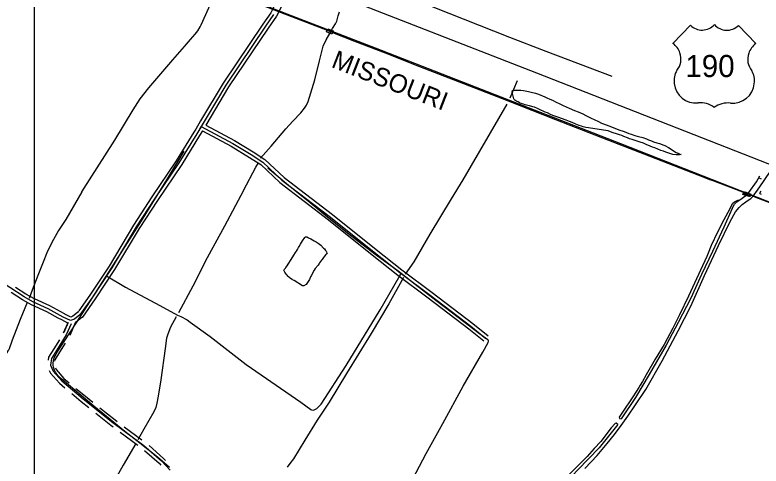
# Model space of a CAD drawing. Extents: x 3281947 to 3319794, y 715894 to 741249.
# Drawn here: x 3291243 to 3294621, y 723513 to 725556 of the extents above; entities that cross this region are included whole.
import ezdxf

# ---------------------------------------------------------------- set-up
doc = ezdxf.new("R2010")
doc.units = 0
for name, color, linetype in [('V-BRDG-OTLN', 7, 'Continuous'), ('V-DTCH-CNTR', 7, 'Continuous'), ('V-GRID-MAJR', 7, 'Continuous'), ('V-RAIL-IDEN', 7, 'Continuous'), ('V-RAIL-TRAK', 7, 'Continuous'), ('V-ROAD-CNTR', 7, 'Continuous'), ('V-ROAD-IDEN', 7, 'Continuous'), ('V-SITE-VEGE', 7, 'Continuous'), ('V-TOPO-SHOR', 7, 'Continuous')]:
    doc.layers.add(name, color=color, linetype=linetype)

msp = doc.modelspace()

# ---------------------------------------------------------------- linework, layer by layer
at = {"layer": 'V-BRDG-OTLN'}
for points in [[(3292653.9, 725479.3), (3292659.4, 725492.5), (3292683.8, 725483.4), (3292678, 725469.1)], [(3294547.7, 724753.5), (3294546.2, 724749.7), (3294544.5, 724745.1), (3294567.7, 724735.7), (3294566.6, 724733.2), (3294538.4, 724743.2), (3294543.2, 724755.1)], [(3294567.7, 724735.7), (3294544.5, 724745.1), (3294546.2, 724749.7), (3294547.7, 724753.5), (3294571.6, 724744.6)], [(3294567.7, 724735.7), (3294571.6, 724744.6), (3294547.7, 724753.5), (3294548, 724754.2), (3294574.4, 724744.5), (3294572.6, 724739.5), (3294570.9, 724734.4)]]:
    msp.add_lwpolyline(points, close=True, dxfattribs=at)
at = {"layer": 'V-DTCH-CNTR'}
for points in [[(3291942.7, 723506.4), (3291889.3, 723554.4), (3291808.9, 723616.7), (3291741, 723670.1), (3291658.5, 723737.3), (3291601, 723783.9), (3291456.8, 723905.8), (3291437.4, 723923), (3291427.6, 723938.1), (3291422.7, 723947), (3291417.8, 723960.8), (3291417.1, 723969.8), (3291417, 723979.4), (3291418.4, 723990.5), (3291421.7, 724002.9), (3291425.1, 724011.2), (3291430.6, 724021.6), (3291437.4, 724033.4), (3291524.3, 724164.9), (3291651.5, 724365.7), (3291657.3, 724374.9), (3291816.3, 724623.3), (3291938.7, 724820.7), (3292009.7, 724939.1)], [(3293013.8, 723398.5), (3293105.3, 723570.9), (3293180.4, 723706.5), (3293272.4, 723875.3), (3293360.5, 724029.3), (3293385.1, 724073.3), (3293387.3, 724079.3), (3293386.7, 724081.1), (3293383.1, 724084.6), (3293346.2, 724111.6), (3293224.2, 724205.2), (3293149.2, 724262.2), (3293054.6, 724335.8), (3292990.9, 724385.3), (3292984.3, 724390.5), (3292878.4, 724468.7), (3292762.3, 724557.5), (3292657.5, 724639.9), (3292579.5, 724705.3), (3292481.3, 724783.5), (3292388.4, 724861.8)], [(3294584.6, 724734.7), (3294604.3, 724761.8), (3294630.9, 724801.3), (3294647.3, 724824.2), (3294669.8, 724855.4), (3294688, 724881.7)], [(3294504.6, 724663.7), (3294521, 724683.8), (3294535.3, 724697), (3294551.1, 724708.9), (3294566.9, 724720), (3294573.7, 724724.9), (3294579.2, 724729.1), (3294584.6, 724734.7)], [(3293822.8, 723502.5), (3293879.2, 723561), (3293924, 723615.3), (3293957, 723657), (3293987.9, 723697.4), (3294017.4, 723739.1), (3294052.5, 723789.9), (3294098.5, 723860.1), (3294173.2, 723989.3), (3294245.9, 724125.5), (3294302, 724237.3), (3294364.9, 724376.2), (3294427.9, 724512.3), (3294480.6, 724619.9), (3294504.6, 724663.7)], [(3291657.3, 724374.9), (3291744.6, 724323.7), (3291898.9, 724239.7), (3291979.8, 724196.7), (3291994.3, 724189.9), (3292022.7, 724175.6), (3292037.3, 724165.3), (3292127.3, 724099.6), (3292290.1, 723973.6), (3292537.4, 723802.5), (3292582.4, 723769), (3292585.9, 723768.3), (3292595.5, 723767), (3292610, 723774.7), (3292618.2, 723782.3), (3292629.2, 723794.1), (3292742.7, 723969.3), (3292895.8, 724220.6), (3292980.5, 724366.6), (3292990.9, 724385.3)]]:
    msp.add_lwpolyline(points, dxfattribs=at)
at = {"layer": 'V-GRID-MAJR'}
msp.add_spline([(3291333.3, 721274), (3291331.5, 727333.8), (3291329.7, 733395.6), (3291328, 739457.3), (3291328, 739459.2)], degree=3, dxfattribs=at)
at = {"layer": 'V-RAIL-TRAK'}
for p, q in [((3294572.6, 724739.5), (3294546.2, 724749.7)), ((3294584.6, 724734.7), (3294572.6, 724739.5))]:
    msp.add_line(p, q, dxfattribs=at)
for points in [[(3292170, 725674.9), (3292307.9, 725621.4), (3292443.6, 725568.5), (3292656.7, 725486.1), (3292680.9, 725476.4), (3292780, 725437.2), (3292919.1, 725383.8), (3293074.5, 725323), (3293273.2, 725245.4), (3293476.3, 725166.5), (3293689.9, 725082.3), (3293930, 724989), (3294117, 724916.3), (3294333.8, 724831.5), (3294391.4, 724809.7)], [(3294546.2, 724749.7), (3294486.1, 724773.3), (3294391.4, 724809.7)], [(3295596.8, 724339.4), (3295590.1, 724342), (3295495.8, 724379), (3295404.7, 724414.1), (3295300, 724455), (3295207.5, 724491), (3295113.3, 724528.4), (3295017.6, 724565.8), (3294919.7, 724603.6), (3294791.3, 724654.3), (3294691.5, 724693.4), (3294596.8, 724729.9), (3294584.6, 724734.7)]]:
    msp.add_lwpolyline(points, dxfattribs=at)
at = {"layer": 'V-ROAD-CNTR'}
for points in [[(3287528.8, 727489.4), (3288159.7, 727246.7), (3289159.6, 726857.6), (3289743.7, 726626.7), (3290210.1, 726446.4), (3290854.7, 726194.3), (3291198.3, 726062.1), (3292329.9, 725616.5), (3292874.1, 725407.4), (3293983.9, 724974.1), (3294772.1, 724664.7), (3295711.6, 724298), (3296794.9, 723876.7), (3297613.5, 723554.1), (3297991.8, 723406.1), (3298815.4, 723086.6), (3299719.3, 722731.4), (3300678.1, 722358.1)], [(3287937.3, 727504.7), (3287942.9, 727501.7), (3288375.3, 727335.2), (3289142.9, 727037.7), (3290162.7, 726638), (3290851.4, 726368), (3291373.2, 726163.1), (3292434, 725750.1), (3293604.8, 725293.3), (3294762.1, 724839.9)], [(3292483.1, 725732.1), (3292453.4, 725669.1), (3292422.6, 725607.3), (3292401.3, 725564.8), (3292365.5, 725513.2), (3292185.2, 725246.4), (3292084, 725076.1)], [(3292510.3, 725719.2), (3292480.4, 725656.1), (3292449.5, 725593.9), (3292427.1, 725549.4), (3292390.3, 725496.3), (3292210.5, 725230.3), (3292107.2, 725056.3)], [(3292414.2, 725557.1), (3292377.9, 725504.7), (3292197.8, 725238.4), (3292066.6, 725017.4), (3291985.7, 724886.6), (3291875.8, 724723.7), (3291792.7, 724596.1), (3291681.9, 724410.9), (3291594.9, 724278.6), (3291537.8, 724198.2), (3291513.6, 724178.7), (3291495.1, 724171.8), (3291462.2, 724188.2), (3291393.9, 724224.7), (3291324.6, 724257.2), (3291285.4, 724279.3), (3291153.5, 724363.4)], [(3292084, 725076.1), (3292061.9, 725038.9)], [(3292107.2, 725056.3), (3292236.5, 724987), (3292321.2, 724936.3), (3292374.4, 724901.7), (3292461.7, 724819.7), (3292680.5, 724652.3), (3292878.5, 724493.4), (3292994.2, 724401.9), (3293132.1, 724299.4), (3293316.3, 724158.1), (3293385.1, 724102.8)], [(3292061.9, 725038.9), (3292053.8, 725025.2), (3291973.1, 724894.8), (3291863.3, 724732), (3291780, 724604.1), (3291669.2, 724418.9), (3291582.6, 724287.1), (3291532.3, 724216.2)], [(3292091.8, 725030.5), (3292079.4, 725009.6), (3291998.3, 724878.5), (3291888.3, 724715.4), (3291805.4, 724588.2), (3291694.6, 724402.9), (3291607.3, 724270.1), (3291548.8, 724187.8), (3291538.6, 724179.6)], [(3292080.5, 725040.7), (3292086.3, 725050.5), (3292229.1, 724974), (3292313.3, 724923.5), (3292365.1, 724889.8), (3292452, 724808.2), (3292671.3, 724640.5), (3292869.1, 724481.7), (3292985, 724390), (3293123, 724287.4), (3293307.1, 724146.3), (3293375.2, 724091.6)], [(3292091.8, 725030.5), (3292221.7, 724960.9), (3292305.3, 724910.8), (3292355.8, 724878), (3292442.3, 724796.8), (3292662, 724628.7), (3292859.8, 724470), (3292975.9, 724378.1), (3293114, 724275.4), (3293297.8, 724134.5), (3293365.2, 724080.3)], [(3291467.7, 724202.2), (3291400.7, 724238.2), (3291331.5, 724270.6), (3291293.1, 724292.2), (3291246.4, 724322)], [(3291439.4, 724183.4), (3291387.2, 724211.3), (3291317.8, 724243.9), (3291277.7, 724266.5), (3291226.7, 724298.9)], [(3291530.9, 724214.3), (3291526.8, 724208.6), (3291506, 724191.9), (3291496, 724188.1), (3291469.1, 724201.5), (3291467.7, 724202.2)], [(3291483.6, 724160.8), (3291455.3, 724174.9), (3291439.4, 724183.4)], [(3291538.6, 724179.6), (3291521.1, 724165.5), (3291518.1, 724164.4)], [(3291498.3, 724156.9), (3291476, 724107), (3291432, 724036.3), (3291409.6, 724000.3), (3291404.8, 723970.7), (3291416.9, 723942.8), (3291455, 723899.4), (3291553, 723817.6), (3291687.2, 723710.7), (3291827.5, 723606.1), (3291906.1, 723536.6), (3291945.7, 723495.5)], [(3291463.6, 724116.1), (3291483.6, 724160.8)], [(3291484.6, 724163.1), (3291464.2, 724117.4)], [(3291518.1, 724164.4), (3291491.6, 724105.2)], [(3291512, 724150.8), (3291491.6, 724105.2)], [(3291444.6, 724084.9), (3291419.3, 724044.2), (3291395.3, 724005.7), (3291393.2, 723993.2)], [(3291444.6, 724084.9), (3291419.3, 724044.2), (3291395.3, 724005.7), (3291393.2, 723993.2)], [(3291470.1, 724069.1), (3291444.8, 724028.3), (3291423.9, 723995), (3291422.9, 723988.4)], [(3291470.1, 724069.1), (3291444.8, 724028.3), (3291423.9, 723995), (3291422.9, 723988.4)], [(3291398.8, 723946.7), (3291404, 723934.6), (3291444.5, 723888.6), (3291469.6, 723867.7)], [(3291398.8, 723946.7), (3291404, 723934.6), (3291444.5, 723888.6), (3291469.6, 723867.7)], [(3291426.4, 723958.6), (3291429.7, 723950.9), (3291465.5, 723910.2), (3291488.8, 723890.7)], [(3291426.4, 723958.6), (3291429.7, 723950.9), (3291465.5, 723910.2), (3291488.8, 723890.7)], [(3291500.3, 723842.1), (3291543.5, 723806), (3291577.9, 723778.6)], [(3291500.3, 723842.1), (3291543.5, 723806), (3291577.9, 723778.6)], [(3291519.5, 723865.1), (3291562.5, 723829.2), (3291596.6, 723802)], [(3291519.5, 723865.1), (3291562.5, 723829.2), (3291596.6, 723802)], [(3291627.9, 723777.1), (3291696.4, 723722.6), (3291706, 723715.4)], [(3291627.9, 723777.1), (3291696.4, 723722.6), (3291706, 723715.4)], [(3291609.2, 723753.6), (3291678.1, 723698.8), (3291688.1, 723691.4)], [(3291609.2, 723753.6), (3291678.1, 723698.8), (3291688.1, 723691.4)], [(3291738.1, 723691.5), (3291818.2, 723631.7)], [(3291738.1, 723691.5), (3291818.2, 723631.7)], [(3291720.1, 723667.4), (3291800.3, 723607.7)], [(3291720.1, 723667.4), (3291800.3, 723607.7)], [(3291850.4, 723605.9), (3291916.5, 723547.5), (3291925.5, 723538.1)], [(3291850.4, 723605.9), (3291916.5, 723547.5), (3291925.5, 723538.1)], [(3291830.5, 723583.4), (3291895.7, 723525.8), (3291903.9, 723517.3)], [(3291830.5, 723583.4), (3291895.7, 723525.8), (3291903.9, 723517.3)]]:
    msp.add_lwpolyline(points, dxfattribs=at)
at = {"layer": 'V-ROAD-IDEN'}
for p, q in [((3294221.8, 725427), (3294300.9, 725508.7)), ((3294596.8, 725425.8), (3294518, 725507.9))]:
    msp.add_line(p, q, dxfattribs=at)
for centre, major_axis, start_param, end_param in [((3294353.6, 725562), (0, -75), 5.502702, 7.121811), ((3294465.5, 725561.4), (0, 75), 2.291842, 3.917604), ((3294166.5, 725353.3), (0, 92.2), 5.045266, 5.638568), ((3294651.7, 725351.8), (0, -92.2), 3.781672, 4.374974), ((3294176.6, 725356.4), (0, 81.7), 4.021008, 5.049788), ((3294641.7, 725355), (0, -81.7), 4.370452, 5.399232), ((3294312.9, 725259.2), (0, -86.5), 4.163028, 4.868958), ((3294504.8, 725258.4), (0, 86.5), 4.551282, 5.257212), ((3294325.8, 725255.7), (0, 98.8), 1.672766, 3.238327), ((3294492, 725255), (0, -98.8), 6.181885, 7.747479), ((3294346.1, 725052.3), (0, 105.6), 5.646836, 6.385311), ((3294470.8, 725051.6), (0, -105.6), 3.034929, 3.773404)]:
    msp.add_ellipse(centre, major_axis=major_axis, ratio=0.99789, start_param=start_param, end_param=end_param, dxfattribs=at)
at = {"layer": 'V-SITE-VEGE'}
for points in [[(3294236, 724933.6), (3294245.2, 724930.6), (3294253.1, 724925.9), (3294258.5, 724924.1), (3294251, 724923), (3294236.7, 724923.1), (3294220.8, 724924.6), (3294212.8, 724926.4), (3294202.8, 724930.3), (3294189.9, 724934.2), (3294178.2, 724938.6), (3294166.9, 724942.5), (3294154, 724948.1), (3294139.8, 724953.3), (3294129.8, 724957.2), (3294118.9, 724962), (3294101, 724969.3), (3294088.9, 724974.5), (3294073, 724980.2), (3294050, 724987.2), (3294037.5, 724991.6), (3294025.8, 724995.1), (3294016.2, 724999.4), (3293998.7, 725005.5), (3293990.3, 725009.4), (3293980.3, 725012.4), (3293970.3, 725016.3), (3293946.1, 725024.2), (3293936, 725027.7), (3293931.4, 725029), (3293929, 725030.7), (3293926.4, 725031.6), (3293838.9, 725045.3), (3293828.1, 725045.9), (3293815.9, 725049), (3293807.2, 725052), (3293797.5, 725055.1), (3293782.5, 725061.6), (3293766.3, 725068.1), (3293752.9, 725073.7), (3293738.3, 725079.3), (3293700.3, 725093.2), (3293678.6, 725100.6), (3293667.7, 725105), (3293653.6, 725111.9), (3293643.1, 725115.8), (3293618.1, 725128.3), (3293609, 725132.6), (3293595.2, 725137.8), (3293587.2, 725139.6), (3293573, 725143.5), (3293564.7, 725146.2), (3293552.1, 725149.3), (3293545, 725151.5), (3293535, 725154.9), (3293527.9, 725158), (3293520.4, 725162.3), (3293516.7, 725164), (3293510.4, 725167.4), (3293505.4, 725170.4), (3293502.5, 725173.4), (3293501.3, 725175.9), (3293499.7, 725181.4), (3293498.1, 725187.7), (3293495.3, 725199.9), (3293493.7, 725207.5), (3293495.9, 725214.2), (3293501.4, 725215.8), (3293516.9, 725215.6), (3293528.2, 725214.6), (3293532.8, 725214.5), (3293545.4, 725213.5), (3293568.4, 725209.5), (3293580.1, 725206.8), (3293598.9, 725201.5), (3293613.1, 725196.3), (3293641.1, 725185.4), (3293654, 725179.4), (3293661.5, 725175.5), (3293679.9, 725167.7), (3293690.7, 725161.7), (3293709.9, 725152.7), (3293725.3, 725146.2), (3293738.2, 725139.7), (3293752, 725134.1), (3293775.4, 725123.7), (3293792.1, 725117.2), (3293813.7, 725107.3), (3293827.9, 725100), (3293850.8, 725088.8), (3293864.6, 725082.3), (3293884.6, 725073.2), (3293898.8, 725066.3), (3293918.8, 725058.5), (3293932.2, 725052.9), (3293958.9, 725042.5), (3293977.3, 725035.5), (3294000.2, 725027.7), (3294011.5, 725023.4), (3294021.9, 725019), (3294033.2, 725015.5)], [(3294033.2, 725015.5), (3294049.1, 725010.3), (3294059.9, 725007.2), (3294066.2, 725005.9), (3294085.9, 725000.6), (3294101.7, 724994.9), (3294111.7, 724991), (3294124.3, 724985), (3294133.4, 724981.9), (3294148.5, 724977.1), (3294161.4, 724973.2), (3294180.2, 724966.6), (3294185.6, 724964.1), (3294201.1, 724956.3), (3294209, 724950.8), (3294219.8, 724943.5), (3294236, 724933.6)], [(3294622.8, 724742.4), (3294616.6, 724746.2), (3294614.5, 724749.2), (3294615.8, 724752.5), (3294621.3, 724757.5)]]:
    msp.add_lwpolyline(points, dxfattribs=at)
msp.add_lwpolyline([(3292507.8, 724353.6), (3292500.3, 724356.6), (3292497.8, 724357.9), (3292490.8, 724362.6), (3292487.9, 724365.2), (3292482, 724369.9), (3292479.1, 724372.4), (3292475.4, 724377.1), (3292473, 724380.9), (3292468, 724387.2), (3292465.1, 724391.5), (3292461.4, 724397.4), (3292461, 724399.9), (3292461.5, 724402.8), (3292463.2, 724404.5), (3292467.5, 724409.1), (3292469.6, 724411.6), (3292476, 724420.3), (3292480.7, 724427.3), (3292493.1, 724448.6), (3292505.6, 724468.6), (3292513.7, 724479.8), (3292517.9, 724486.4), (3292522.2, 724493.5), (3292527, 724502.7), (3292530, 724507.7), (3292535.5, 724517.7), (3292545, 724533.5), (3292555.2, 724547.6), (3292558.2, 724550.5), (3292560.3, 724550.9), (3292564.5, 724550.8), (3292567.8, 724549.1), (3292572.4, 724546.6), (3292582, 724541.8), (3292597.4, 724532.8), (3292606.2, 724528.9), (3292616.6, 724522.5), (3292621.5, 724518.2), (3292627.8, 724512.7), (3292639.8, 724500.4), (3292644.3, 724496.1), (3292648.9, 724489.4), (3292651.8, 724486), (3292655.5, 724480.9), (3292655.9, 724478.8), (3292654.1, 724474.6), (3292650.7, 724470.5), (3292644.3, 724463.4), (3292640.1, 724458), (3292633.6, 724448.4), (3292631.1, 724445.5), (3292622.1, 724433.9), (3292620.8, 724431), (3292615.3, 724423.5), (3292602.1, 724407.3), (3292597.4, 724400.7), (3292583.6, 724375.3), (3292581, 724369.8), (3292576.3, 724358.6), (3292571.1, 724349), (3292567.7, 724344), (3292564.7, 724340.3), (3292560.9, 724335.7), (3292550.7, 724330), (3292547.8, 724329.2), (3292545.3, 724328.8)], close=True, dxfattribs=at)
at = {"layer": 'V-TOPO-SHOR'}
for p, q in [((3293485.6, 725179.9), (3293518.7, 725258.3)), ((3294622.7, 724811.6), (3294609.6, 724817.8))]:
    msp.add_line(p, q, dxfattribs=at)
for points in [[(3291546.3, 724755.1), (3291696.2, 724989.2), (3291778, 725126.5), (3291809.5, 725176.5), (3291848.9, 725226.2), (3291957.5, 725351.9), (3292010.9, 725413.4), (3292038.1, 725444.5), (3292059, 725468.8), (3292071.2, 725483.9), (3292081.7, 725501.6), (3292087.1, 725510.2), (3292134.6, 725618), (3292159.1, 725681.9), (3292193.8, 725775.5)], [(3293946.3, 725277.6), (3293648.5, 725389.8), (3293484, 725454.2), (3293136.2, 725591.4), (3292912.6, 725682.6)], [(3292355.1, 724906.9), (3292402.5, 724961.6), (3292470.3, 725039.6), (3292501.5, 725074.5), (3292537.7, 725112.2), (3292554.4, 725134.3), (3292563.6, 725146.7), (3292571.1, 725163.7), (3292600.5, 725261.5), (3292621.3, 725347.3), (3292639.1, 725414.1), (3292652.1, 725443.2), (3292669.1, 725471.2), (3292681.3, 725494.4), (3292695.1, 725515.4), (3292699.8, 725527.9), (3292704.1, 725539.2), (3292706.7, 725550.9), (3292712.3, 725569.7)], [(3293469.6, 725151.9), (3293270.2, 724809.6), (3293217.9, 724723.1)], [(3292277.2, 724760.5), (3292333.3, 724866.2), (3292345.8, 724886.5)], [(3294525.1, 724718.1), (3294552.2, 724738.1), (3294559.1, 724744.5), (3294565.2, 724752.1), (3294599.4, 724800.4), (3294615.2, 724827.5)], [(3291546.3, 724755.1), (3291473.5, 724630.3), (3291440.6, 724579.1), (3291410.1, 724526.2), (3291387.8, 724479.2), (3291371.5, 724435.9), (3291346.9, 724375.9), (3291321.8, 724309.9), (3291307.9, 724272.1)], [(3292277.2, 724760.5), (3292192.1, 724600), (3292114.1, 724456.7), (3292047.9, 724327.1), (3291983.7, 724206.8)], [(3293217.9, 724723.1), (3293121.6, 724562.5), (3293048.9, 724437.6), (3293010.4, 724382.2)], [(3294479.3, 724678.2), (3294492.2, 724703.1), (3294500.5, 724710.1), (3294509.4, 724714.3), (3294514.9, 724716.4), (3294525.1, 724718.1)], [(3294489.7, 724679.6), (3294500.6, 724699), (3294511.5, 724709.4), (3294525.1, 724718.1)], [(3294479.3, 724678.2), (3294451.3, 724628.2), (3294423.3, 724572.8), (3294395.3, 724512.5), (3294381.7, 724476.5), (3294375.5, 724462.7), (3294346.2, 724399.6), (3294310, 724322), (3294292.2, 724282.6), (3294251.9, 724197.4), (3294221.8, 724138.4), (3294181.5, 724063.6), (3294141.8, 723997.7), (3294100.7, 723927), (3294084.3, 723895.8), (3294072.7, 723879.2), (3294067.9, 723868.8), (3294039.8, 723826.5), (3293993.2, 723757.8), (3293978.1, 723734.2), (3293980, 723729.1), (3293986.8, 723726.6)], [(3294489.7, 724679.6), (3294452.2, 724595.1), (3294400, 724484.3), (3294351.3, 724381.3), (3294302.6, 724273), (3294245.6, 724162.8), (3294191.6, 724060.9), (3294114.5, 723928.1), (3294051.6, 723823.2), (3293986.8, 723726.6)], [(3293001.5, 724367.6), (3292935.6, 724247.9), (3292855.1, 724113.5), (3292744.7, 723932.1), (3292665.5, 723801.9), (3292612, 723721), (3292556.2, 723630), (3292504, 723546.1), (3292488.1, 723524.7), (3292475.7, 723508)], [(3291299, 724253.4), (3291266.9, 724176.9), (3291230.6, 724083.6), (3291215.5, 724040.3), (3291212, 724034.9), (3291161.4, 723956.4), (3291116.2, 723883.2), (3291108, 723867.8), (3291102.8, 723852.3), (3291099.9, 723839.9), (3291099.3, 723838.1), (3291114.8, 723707.8), (3291135.4, 723539.6), (3291157.9, 723332.9), (3291164.1, 723273.7), (3291165.4, 723257.7), (3291163.7, 723243.4), (3291160.8, 723228), (3291107.5, 723118.1), (3291100.7, 723106.2)], [(3291973.4, 724189.4), (3291948.2, 724142.2), (3291934.8, 724110.7), (3291930.1, 724091.8), (3291922.7, 724045.5), (3291904.5, 723903.1), (3291891.9, 723829.6), (3291885.6, 723797.5), (3291880.9, 723779.1), (3291872.2, 723758.9), (3291826.4, 723680.4), (3291799.4, 723632.7)], [(3293971.5, 723701), (3293964.9, 723708.3), (3293960.5, 723705.8), (3293942.6, 723687), (3293894.6, 723625.2), (3293864.4, 723593.3), (3293832.8, 723557.2), (3293787.4, 723510.6), (3293735.9, 723459.2), (3293701.6, 723421.7), (3293665.9, 723382.8), (3293645.9, 723360.6), (3293627.4, 723337.7), (3293606.9, 723309.9), (3293598.6, 723294), (3293583, 723251.7), (3293563.3, 723194.2), (3293569.3, 723189.7), (3293575.4, 723194)], [(3293971.5, 723701), (3293888.4, 723596.6), (3293791.6, 723495.7), (3293716, 723416.9), (3293662.3, 723358.4), (3293630.5, 723319.6), (3293607.6, 723280.3), (3293591.2, 723239.8), (3293575.4, 723194)], [(3291791.2, 723615.3), (3291733.7, 723518.1), (3291663.3, 723393.9), (3291588.7, 723262.4), (3291500.1, 723107.8), (3291405, 722944.9), (3291392, 722922.8)]]:
    msp.add_lwpolyline(points, dxfattribs=at)

# ---------------------------------------------------------------- texts
at = {"layer": 'V-RAIL-IDEN'}
msp.add_text('MISSOURI', height=83, rotation=338.7178, dxfattribs=at).set_placement((3292670.9, 725320.8))
at = {"layer": 'V-ROAD-IDEN'}
msp.add_text('190', height=100, dxfattribs=at).set_placement((3294277.8, 725274.4))

doc.saveas('drawing.dxf')
